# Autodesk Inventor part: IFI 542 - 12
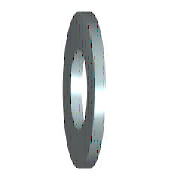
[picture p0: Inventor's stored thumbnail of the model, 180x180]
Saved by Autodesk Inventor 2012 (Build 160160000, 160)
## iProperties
Created: 2011-02
Part Number: IFI 542 - 12
Material: Steel, Mild
Description: Circular Washer
Document SubType Name: Modeling
Standard: IFI 542
Designer: jrr70267
Standards Organization: ANSI
Language: en-US
Size Designation: 12
Categories: <MemberInstance><Categories><Category DisplayName="Fasteners" InternalName="e4da775c-781d-43d5-af7c-5136215cf5a6" Mnemonic="FSTN"><Category DisplayName="Washers
Density: 1 g/cm^3
IsCustomPart: 0
Author: jrr70267
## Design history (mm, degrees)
workaxis "Work Axis1"
workplane "Work Plane1"
body "Solid1"
sketch "Sketch"
  geometry: C1 r 13.5 at (0, 0); C2 r 7 at (0, 0); 1 further point
  constraints: 2 centre point, 2 coincident
  dimensions: "d0" = 14 diameter of C2 (= SD1); "d1" = 27 diameter of C1 (= SD2)
extrude "Body" new body sketch "Sketch" distance "d2" = 4.6 (= SD); taper "d3" = 0 deg
other parameters: "SD1" = 14 [user parameter; used in 1 equation term], "SD2" = 27 [user parameter; used in 1 equation term], "SD" = 4.6 [user parameter; used in 1 equation term], "d4" = 0, "d5" = 0, "d6" = 0, "d7" = 0, "NND" = 12 [user parameter]
